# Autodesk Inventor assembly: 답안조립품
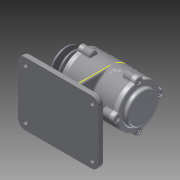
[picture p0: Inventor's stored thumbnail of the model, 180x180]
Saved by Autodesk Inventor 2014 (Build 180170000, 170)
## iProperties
Created: 2015-12
Part Number: 답안조립품
Document SubType Name: Assembly
Designer: test_24
Author: test_24
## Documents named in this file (11)
- C:\Users\test_24\Desktop\451207V1034\답안조립품.iam
- C:\Users\test_24\Desktop\451207V1034\1-본체.ipt
- C:\Users\test_24\Desktop\451207V1034\451207V1034\V-벨트풀리.ipt
- C:\Users\test_24\Desktop\451207V1034\451207V1034\너트 M12x1.25.ipt
- C:\Users\test_24\Desktop\451207V1034\451207V1034\베어링 6204.ipt
- C:\Users\test_24\Desktop\451207V1034\451207V1034\볼트 M4 x 12.ipt
- C:\Users\test_24\Desktop\451207V1034\451207V1034\오일실.ipt
- C:\Users\test_24\Desktop\451207V1034\451207V1034\축.ipt
- C:\Users\test_24\Desktop\451207V1034\451207V1034\커버.ipt
- C:\Users\test_24\Desktop\451207V1034\451207V1034\커버2.ipt
- C:\Users\test_24\Desktop\451207V1034\451207V1034\키(4 x 4 x 12).ipt
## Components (7 placed, 6 different names)
1. 1-본체:1
2. V-벨트풀리:1
3. KS B 1012 클래스 1 일반 - 미터 M12x1.25:1 — 플러쉬:1
4. KS B 2023 6204 - 20 x 47 x 14:1
5. KS B 2804 D D - 20 32 8:1
6. KS B 1311 (I) 4 x 4 x 12:1
7. KS B 2023 6204 - 20 x 47 x 14:2
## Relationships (1: Flush 1)
- 플러쉬:1 [Flush]: KS B 1012 클래스 1 일반 - 미터 M12x1.25:1
